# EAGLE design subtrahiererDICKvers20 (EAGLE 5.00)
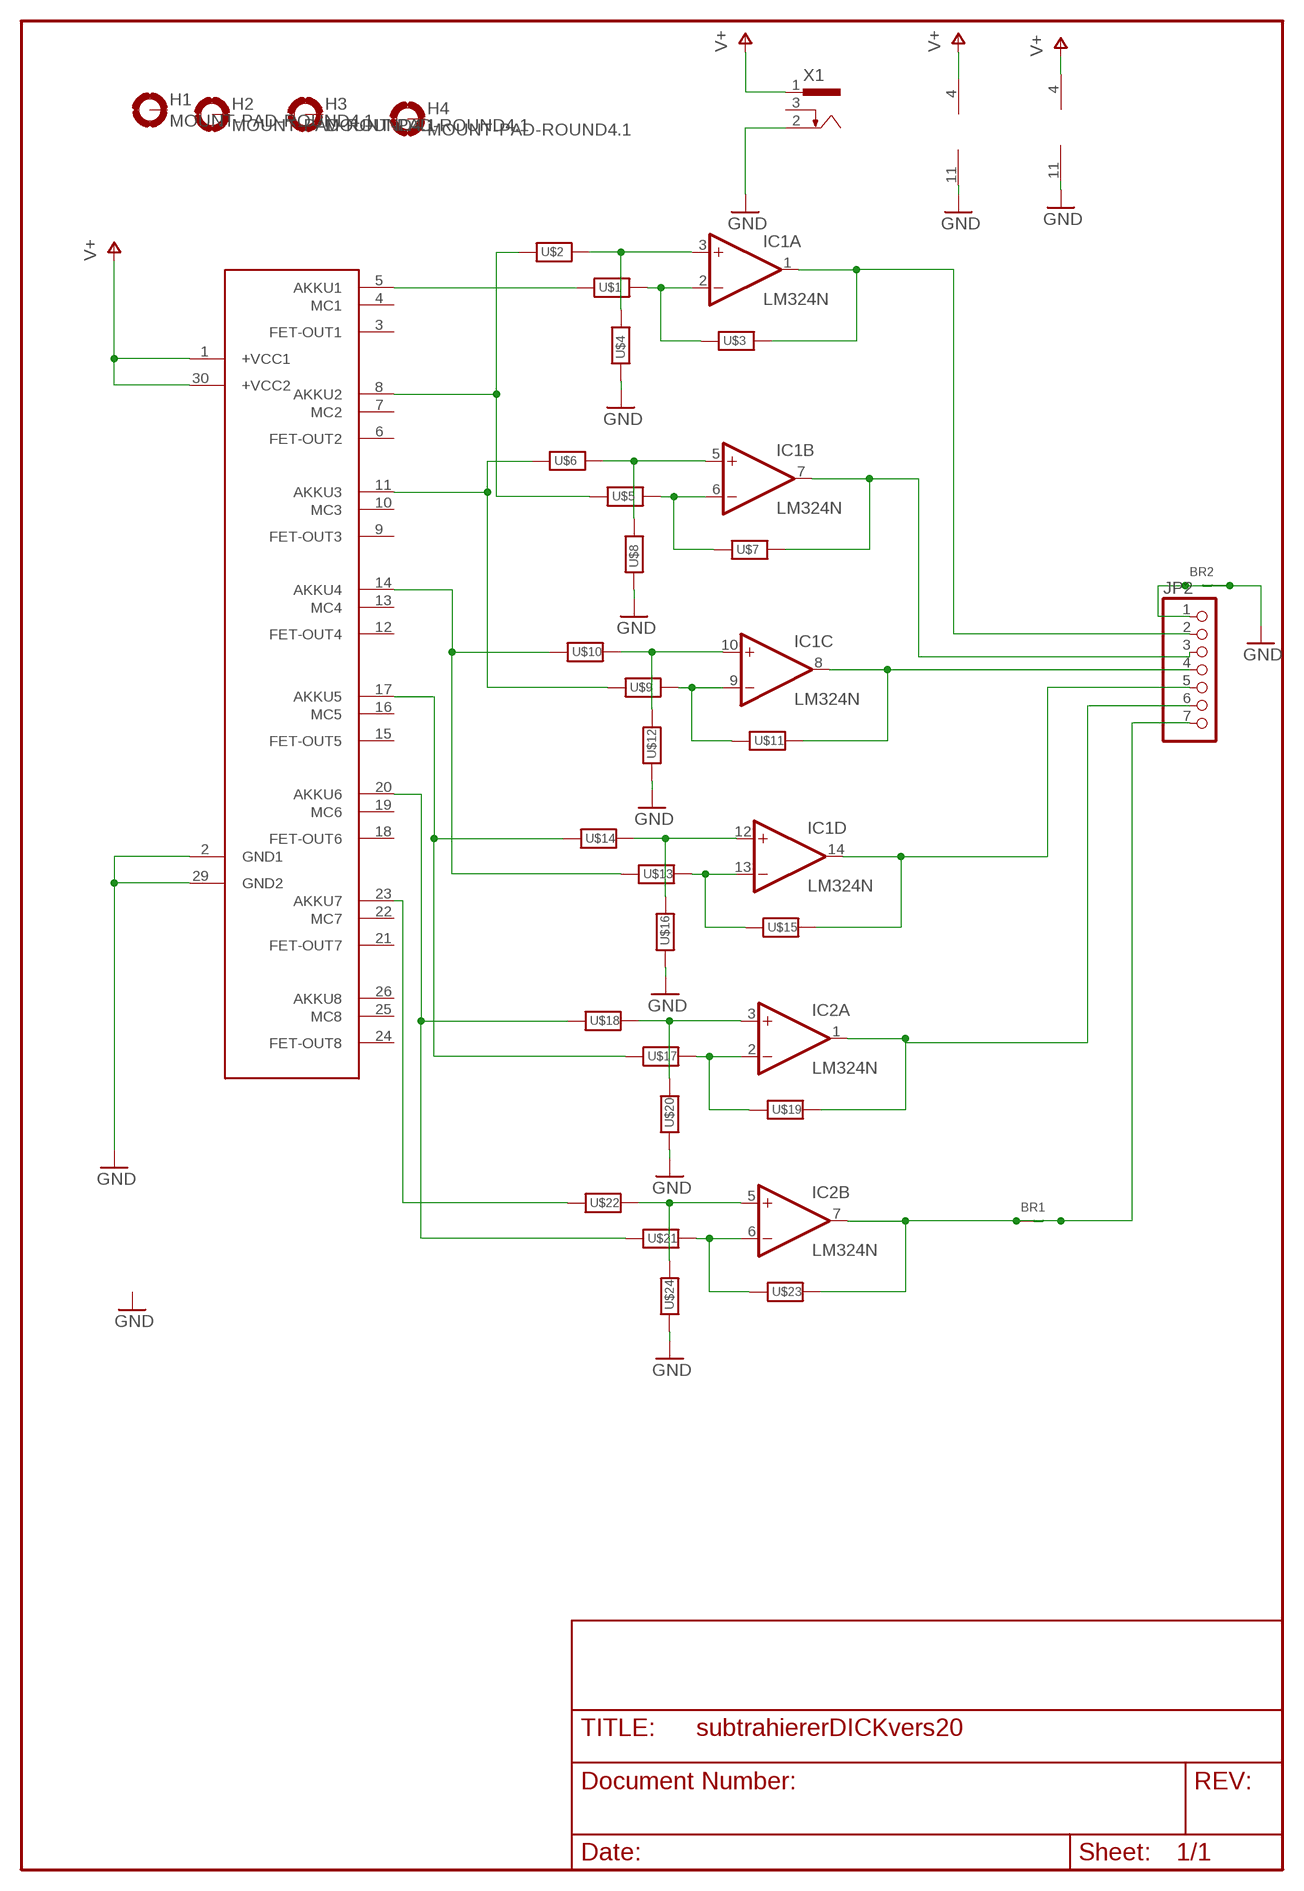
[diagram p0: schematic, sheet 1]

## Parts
BR1  BRUE8E  [BRUE8E]
BR2  BRUE8E  [BRUE8E]
H1  MOUNT-PAD-ROUND4.1  [4,1-PAD]
H2  MOUNT-PAD-ROUND4.1  [4,1-PAD]
H3  MOUNT-PAD-ROUND4.1  [4,1-PAD]
H4  MOUNT-PAD-ROUND4.1  [4,1-PAD]
IC1  LM324N  [DIL14]
IC2  LM324N  [DIL14]
JP2  PINHD-1X7  [1X07]
U$1  R4E  [R-4E]
U$2  R4E  [R-4E]
U$3  R4E  [R-4E]
U$4  R4E  [R-4E]
U$5  R4E  [R-4E]
U$6  R4E  [R-4E]
U$7  R4E  [R-4E]
U$8  R4E  [R-4E]
U$9  R4E  [R-4E]
U$10  R4E  [R-4E]
U$11  R4E  [R-4E]
U$12  R4E  [R-4E]
U$13  R4E  [R-4E]
U$14  R4E  [R-4E]
U$15  R4E  [R-4E]
U$16  R4E  [R-4E]
U$17  R4E  [R-4E]
U$18  R4E  [R-4E]
U$19  R4E  [R-4E]
U$20  R4E  [R-4E]
U$21  R4E  [R-4E]
U$22  R4E  [R-4E]
U$23  R4E  [R-4E]
U$24  R4E  [R-4E]
U$25  BALANCER1  [1X30]
X1  733980-62  [733980-62]

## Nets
GND: BR2.1 BR2.2 IC1.11(P:V-) IC2.11(P:V-) JP2.1 U$4.1 U$8.1 U$12.1 U$16.1 U$20.1 U$24.1 U$25.2(GND1) U$25.29(GND2) X1.2
N$1: IC1.3(A:+IN) U$2.2 U$4.2
N$2: IC1.2(A:-IN) U$1.2 U$3.1
N$3: IC1.1(A:OUT) JP2.2 U$3.2
N$4: U$2.1 U$5.1 U$25.8(AKKU2)
N$5: IC1.5(B:+IN) U$6.2 U$8.2
N$6: IC1.6(B:-IN) U$5.2 U$7.1
N$7: IC1.7(B:OUT) JP2.3 U$7.2
N$8: U$1.1 U$25.5(AKKU1)
N$9: IC1.10(C:+IN) U$10.2 U$12.2
N$10: IC1.9(C:-IN) U$9.2 U$11.1
N$11: IC1.8(C:OUT) JP2.4 U$11.2
N$12: U$6.1 U$9.1 U$25.11(AKKU3)
N$13: IC1.12(D:+IN) U$14.2 U$16.2
N$14: IC1.13(D:-IN) U$13.2 U$15.1
N$15: IC1.14(D:OUT) JP2.5 U$15.2
N$17: IC2.3(A:+IN) U$18.2 U$20.2
N$18: IC2.2(A:-IN) U$17.2 U$19.1
N$19: IC2.1(A:OUT) JP2.6 U$19.2
N$21: U$18.1 U$21.1 U$25.20(AKKU6)
N$22: IC2.5(B:+IN) U$22.2 U$24.2
N$23: IC2.6(B:-IN) U$21.2 U$23.1
N$24: BR1.1 BR1.2 IC2.7(B:OUT) JP2.7 U$23.2
N$25: U$22.1 U$25.23(AKKU7)
N$26: U$10.1 U$13.1 U$25.14(AKKU4)
N$27: U$14.1 U$17.1 U$25.17(AKKU5)
V+: IC1.4(P:V+) IC2.4(P:V+) U$25.1(+VCC1) U$25.30(+VCC2) X1.1
Unconnected: H1.B4,1(MOUNT) H2.B4,1(MOUNT) H3.B4,1(MOUNT) H4.B4,1(MOUNT) IC2.8(C:OUT) IC2.9(C:-IN) IC2.10(C:+IN) IC2.12(D:+IN) IC2.13(D:-IN) IC2.14(D:OUT) U$25.3(FET-OUT1) U$25.4(MC1) U$25.6(FET-OUT2) U$25.7(MC2) U$25.9(FET-OUT3) U$25.10(MC3) U$25.12(FET-OUT4) U$25.13(MC4) U$25.15(FET-OUT5) U$25.16(MC5) U$25.18(FET-OUT6) U$25.19(MC6) U$25.21(FET-OUT7) U$25.22(MC7) U$25.24(FET-OUT8) U$25.25(MC8) U$25.26(AKKU8) X1.3

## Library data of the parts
BR1 BR2 = raf_discrete:BRUE8E
H1-H4 = holes:MOUNT-PAD-ROUND: MOUNTING PAD, round
IC1 IC2 = linear:LM324: OP AMP
JP2 = pinhead:PINHD-1X7: PIN HEADER
U$1-U$24 = raf_discrete:R: Standard-Widerstand 1/4W, Baugrößen 4e - 8e
U$25 = balancer-mega8:BALANCER1
X1 = con-conrad:73398?: FEMALE PRINT CONNECTOR Niedervolt-Steckverbinder Distributor Conrad

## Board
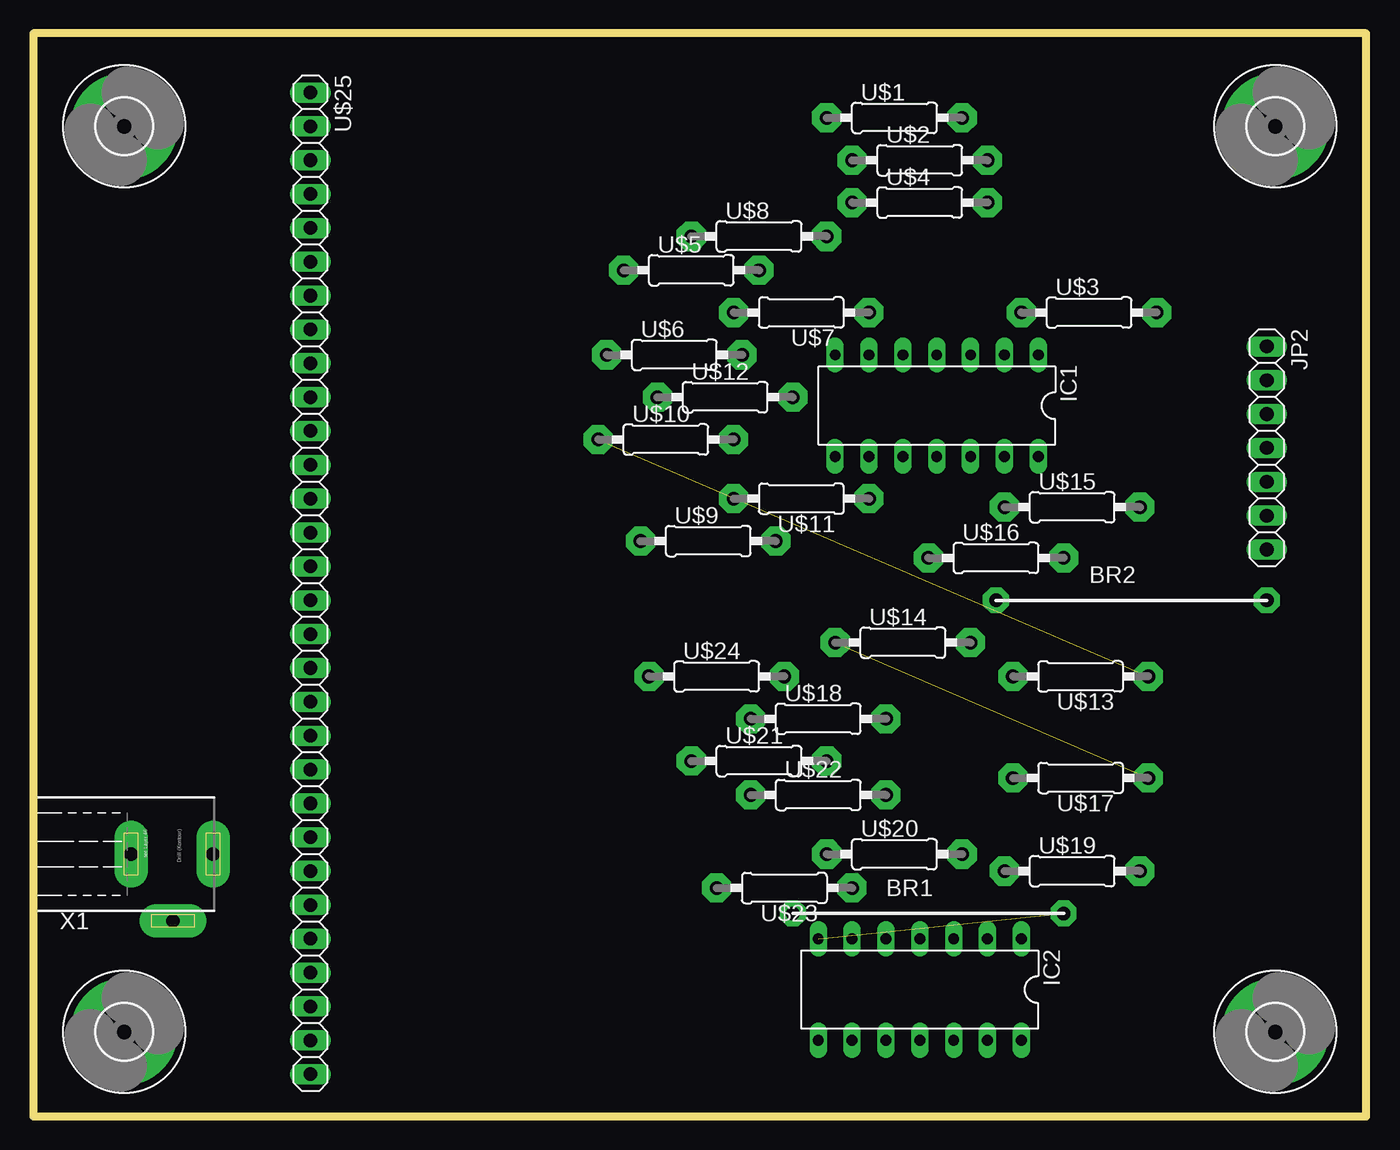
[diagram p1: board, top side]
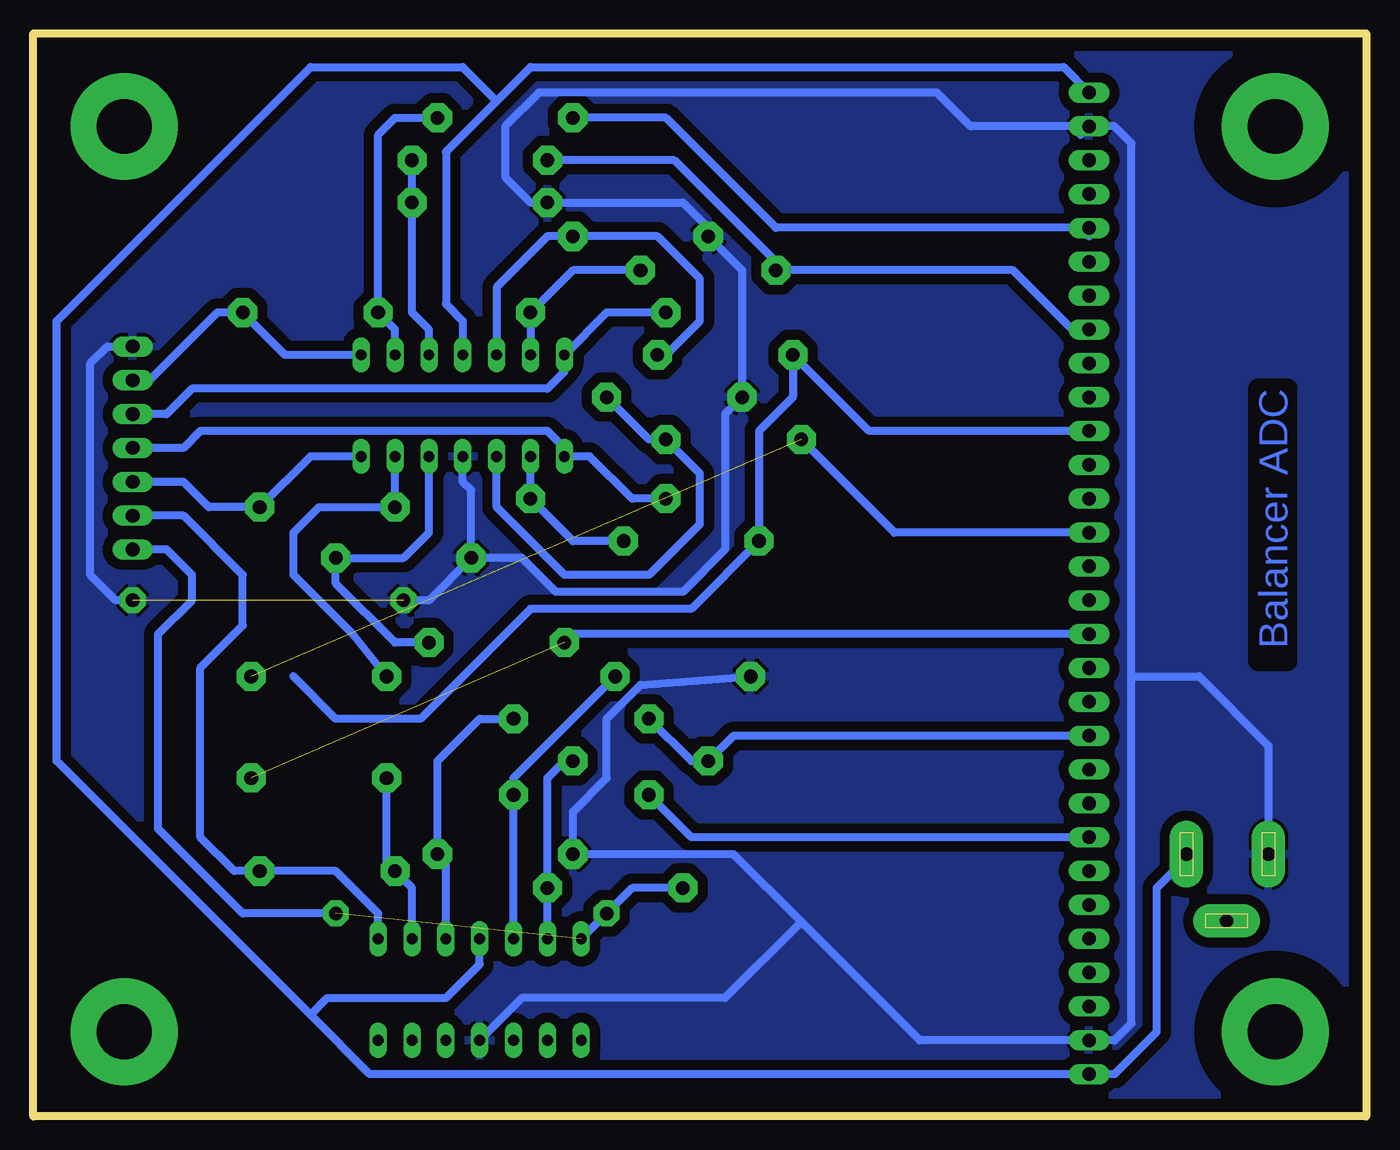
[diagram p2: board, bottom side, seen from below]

Size 100 x 81.27 mm. Coordinates in mm from the lower left corner, seen from the top.
Outline: 0,0 100,0 100,81.27 0,81.27 0,0
Copper layers (1*16): Top 0.035mm / dielectric 1.5mm / Bottom 0.035mm
Design rules "default *": minimum track width 10mil, minimum drill 24mil, track to track 30mil, track to pad 30mil, pad to pad 8mil, via to via 8mil, smd to smd 8mil, copper to edge 40mil, drill to drill 8mil, minimum pad ring 10mil, minimum via ring 8mil, stop-mask expansion 4mil, vias tented up to drill 0mil, thermal gap 10mil

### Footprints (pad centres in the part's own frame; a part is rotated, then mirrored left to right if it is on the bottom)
BRUE8E = drill 1.016 pad 1.93 octagon: 1 0,0; 2 20.32,0
4,1-PAD = drill 4.1 pad 8 round: B4,1 0,0
DIL14 = drill 0.813 long: 1 -7.62,-3.81; 2 -5.08,-3.81; 3 -2.54,-3.81; 4 0,-3.81; 5 2.54,-3.81; 6 5.08,-3.81; 7 7.62,-3.81; 8 7.62,3.81; 9 5.08,3.81; 10 2.54,3.81; 11 0,3.81; 12 -2.54,3.81; 13 -5.08,3.81; 14 -7.62,3.81
1X07 = drill 1.016 long: 1 -7.62,0; 2 -5.08,0; 3 -2.54,0; 4 0,0; 5 2.54,0; 6 5.08,0; 7 7.62,0
R-4E = drill 1.016 pad 2.184 octagon: 1 -5.08,0; 2 5.08,0
1X30 = drill 1.016 long: 1 -36.83,0; 2 -34.29,0; 3 -31.75,0; 4 -29.21,0; 5 -26.67,0; 6 -24.13,0; 7 -21.59,0; 8 -19.05,0; 9 -16.51,0; 10 -13.97,0; 11 -11.43,0; 12 -8.89,0; 13 -6.35,0; 14 -3.81,0; 15 -1.27,0; 16 1.27,0; 17 3.81,0; 18 6.35,0; 19 8.89,0; 20 11.43,0; 21 13.97,0; 22 16.51,0; 23 19.05,0; 24 21.59,0; 25 24.13,0; 26 26.67,0; 27 29.21,0; 28 31.75,0; 29 34.29,0; 30 36.83,0
733980-62 = drill 1 pad 2.5 long: 1 0,8.57; 2 0,2.42; 3 5,5.57

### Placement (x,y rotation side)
BR1  56.98,15.24 0 top
BR2  72.22,38.73 0 top
H1  6.82,6.34 0 top
H2  93.18,6.34 0 top
H3  6.82,74.29 0 top
H4  93.18,74.29 0 top
IC1  67.78,53.34 180 top
IC2  66.51,9.52 180 top
JP2  92.55,50.16 270 top
U$1  64.61,74.92 0 top
U$2  66.51,71.75 0 top
U$3  79.21,60.32 0 top
U$4  66.51,68.57 0 top
U$5  49.37,63.5 0 top
U$6  48.09,57.15 0 top
U$7  57.62,60.32 180 top
U$8  54.45,66.03 0 top
U$9  50.63,43.18 0 top
U$10  47.46,50.8 0 top
U$11  57.62,46.35 180 top
U$12  51.91,53.97 0 top
U$13  78.58,33.02 180 top
U$14  65.24,35.55 0 top
U$15  77.94,45.72 0 top
U$16  72.22,41.91 0 top
U$17  78.58,25.39 180 top
U$18  58.89,29.84 0 top
U$19  77.94,18.41 0 top
U$20  64.61,19.68 0 top
U$21  54.45,26.66 0 top
U$22  58.89,24.12 0 top
U$23  56.35,17.14 180 top
U$24  51.27,33.02 0 top
U$25  20.79,40 270 top
X1  4.92,19.68 270 top

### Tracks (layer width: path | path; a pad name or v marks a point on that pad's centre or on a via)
GND  (1 unrouted)
  Bottom 0.61: IC1.11 67.78,47.62 67.14,46.98 U$16.1 | 42.38,14.6 47.46,19.68 U$20.1 59.52,22.86 56.98,25.39 56.98,29.84 54.45,32.38 U$24.1 | IC2.11 63.34,8.89 48.09,8.89 42.38,14.6 | U$16.1 63.34,41.91 60.8,39.37 51.27,39.37 48.09,42.54 48.09,52.7 U$12.1 46.82,63.5 U$8.1 49.37,66.67 51.27,68.57 U$4.1 62.7,68.57 64.61,70.48 64.61,74.29 62.06,76.83 32.22,76.83 29.68,74.29 22.06,74.29 21.42,73.66 U$25.2 18.88,74.29 17.61,73.02 17.61,33.02 | 42.38,14.6 33.49,5.71 U$25.29 18.88,5.71 17.61,6.98 17.61,33.02 | X1.2 7.33,27.81 12.54,33.02 17.61,33.02 | BR2.1 70.32,38.73 U$16.1 | JP2.1 94.45,57.78 95.72,56.51 95.72,40.64 93.81,38.73 BR2.2
  pour Bottom: 0.47,80.64 99.53,80.64 99.53,0.63 0.47,0.63
N$1
  Bottom 0.61: IC1.3 70.32,59.05 71.59,60.32 U$4.2 72.22,68.57 71.59,69.21 U$2.2
N$2
  Bottom 0.61: U$1.2 72.86,74.92 74.13,73.66 U$3.1 72.86,59.05 IC1.2
N$3
  Bottom 0.61: IC1.1 81.11,57.15 U$3.2 86.19,60.32 91.28,55.24 JP2.2
N$4
  Bottom 0.61: U$25.8 22.06,59.05 26.5,63.5 U$5.1 44.28,64.13 51.91,71.75 U$2.1
N$5
  Bottom 0.61: IC1.5 65.24,62.23 61.43,66.03 U$8.2 53.17,66.03 50,62.86 50,59.69 52.54,57.15 U$6.2
N$6
  Bottom 0.61: IC1.6 U$7.1 59.52,63.5 U$5.2
N$7
  Bottom 0.61: U$7.2 56.98,60.32 IC1.7 60.16,55.88 61.43,54.61 88.1,54.61 90,52.7 JP2.3
N$8
  Bottom 0.61: U$25.5 20.79,66.03 21.42,66.67 44.28,66.67 52.54,74.92 U$1.1
N$9
  Bottom 0.61: U$12.2 53.81,50.8 U$10.2 50,48.26 50,44.45 53.81,40.64 60.16,40.64 65.24,45.72 IC1.10
N$10
  Bottom 0.61: IC1.9 U$11.1 59.52,43.18 U$9.2
N$11
  Bottom 0.61: U$11.2 55.08,46.35 58.25,49.53 IC1.8 60.16,50.16 61.43,51.43 87.47,51.43 88.73,50.16 JP2.4
N$12
  Bottom 0.61: U$25.11 37.3,51.43 U$6.1 43.02,53.97 45.55,51.43 U$9.1 50.63,38.1 62.7,38.1 70.95,29.84 77.3,29.84 80.48,33.02
N$13
  Bottom 0.61: IC1.12 70.32,43.81 72.22,41.91 U$16.2 77.3,40 72.86,35.55 U$14.2
N$14
  Bottom 0.61: U$15.1 IC1.13 | U$15.1 72.86,45.08 | U$15.1 78.58,45.72 80.48,43.81 80.48,40.64 76.03,36.19 U$13.2
N$15
  Bottom 0.61: IC1.14 79.21,49.53 U$15.2 86.83,45.72 88.73,47.62 JP2.5
N$17
  Bottom 0.61: IC2.3 69.05,19.04 U$20.2 69.69,26.66 66.51,29.84 U$18.2
N$18
  Bottom 0.61: IC2.2 71.59,17.14 U$19.1 73.5,18.41 U$17.2
N$19
  Bottom 0.61: IC2.1 74.13,15.24 77.3,18.41 U$19.2 84.92,18.41 87.47,20.95 87.47,33.65 84.29,36.83 84.29,40.64 88.73,45.08 JP2.6
N$21
  Bottom 0.61: U$18.1 50.63,26.66 U$21.1 47.46,28.57 U$25.20
N$22
  Bottom 0.61: IC2.5 U$22.2 63.97,25.39 U$24.2
N$23
  Bottom 0.61: U$21.2 60.16,26.66 61.43,25.39 U$23.1 IC2.6
N$24  (1 unrouted)
  Bottom 0.61: U$23.2 55.08,17.14 BR1.1 IC2.7 | BR1.2 84.29,15.24 90.64,21.58 90.64,36.19 88.1,38.73 88.1,40.64 90,42.54 JP2.7
N$25
  Bottom 0.61: U$25.23 50.63,20.95 U$22.1
N$26  (1 unrouted)
  Bottom 0.61: U$13.1 84.29,33.02 | U$25.14 35.39,43.81 U$10.1
N$27  (1 unrouted)
  Bottom 0.61: U$25.17 59.52,36.19 U$14.1
V+
  Bottom 0.61: IC1.4 67.78,59.69 69.05,60.96 69.05,72.38 65.24,76.19 | IC2.4 66.51,11.43 69.05,8.89 77.94,8.89 79.21,7.62 | 65.24,76.19 62.7,78.73 22.7,78.73 U$25.1 | 65.24,76.19 67.78,78.73 79.21,78.73 98.26,59.69 98.26,26.66 79.21,7.62 | 79.21,7.62 74.77,3.17 U$25.30 18.88,3.17 15.71,6.34 15.71,17.14 13.17,19.68 X1.1

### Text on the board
Bottom: Balancer ADC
